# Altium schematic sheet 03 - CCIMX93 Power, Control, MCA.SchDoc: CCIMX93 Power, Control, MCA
size A3; PageSetup: Record=PageOptions¦CenterHorizontal=True¦CenterVertical=True¦PrintScale=0.70¦XCorrection=1.00¦YCorrection=1.00¦PrintKind=0¦BorderSize=5000000¦LeftOffset=0¦BottomOffset=0¦Orientation=2¦PaperLength=4200¦PaperWidth=2970¦Scale=100¦PaperSource=7¦PrintQuality=600¦MediaType=1¦DitherType=10¦PaperKind=A4¦PrintScaleMode=1; Author: Juan Anzola; SheetNumber: 3; SheetTotal: 20
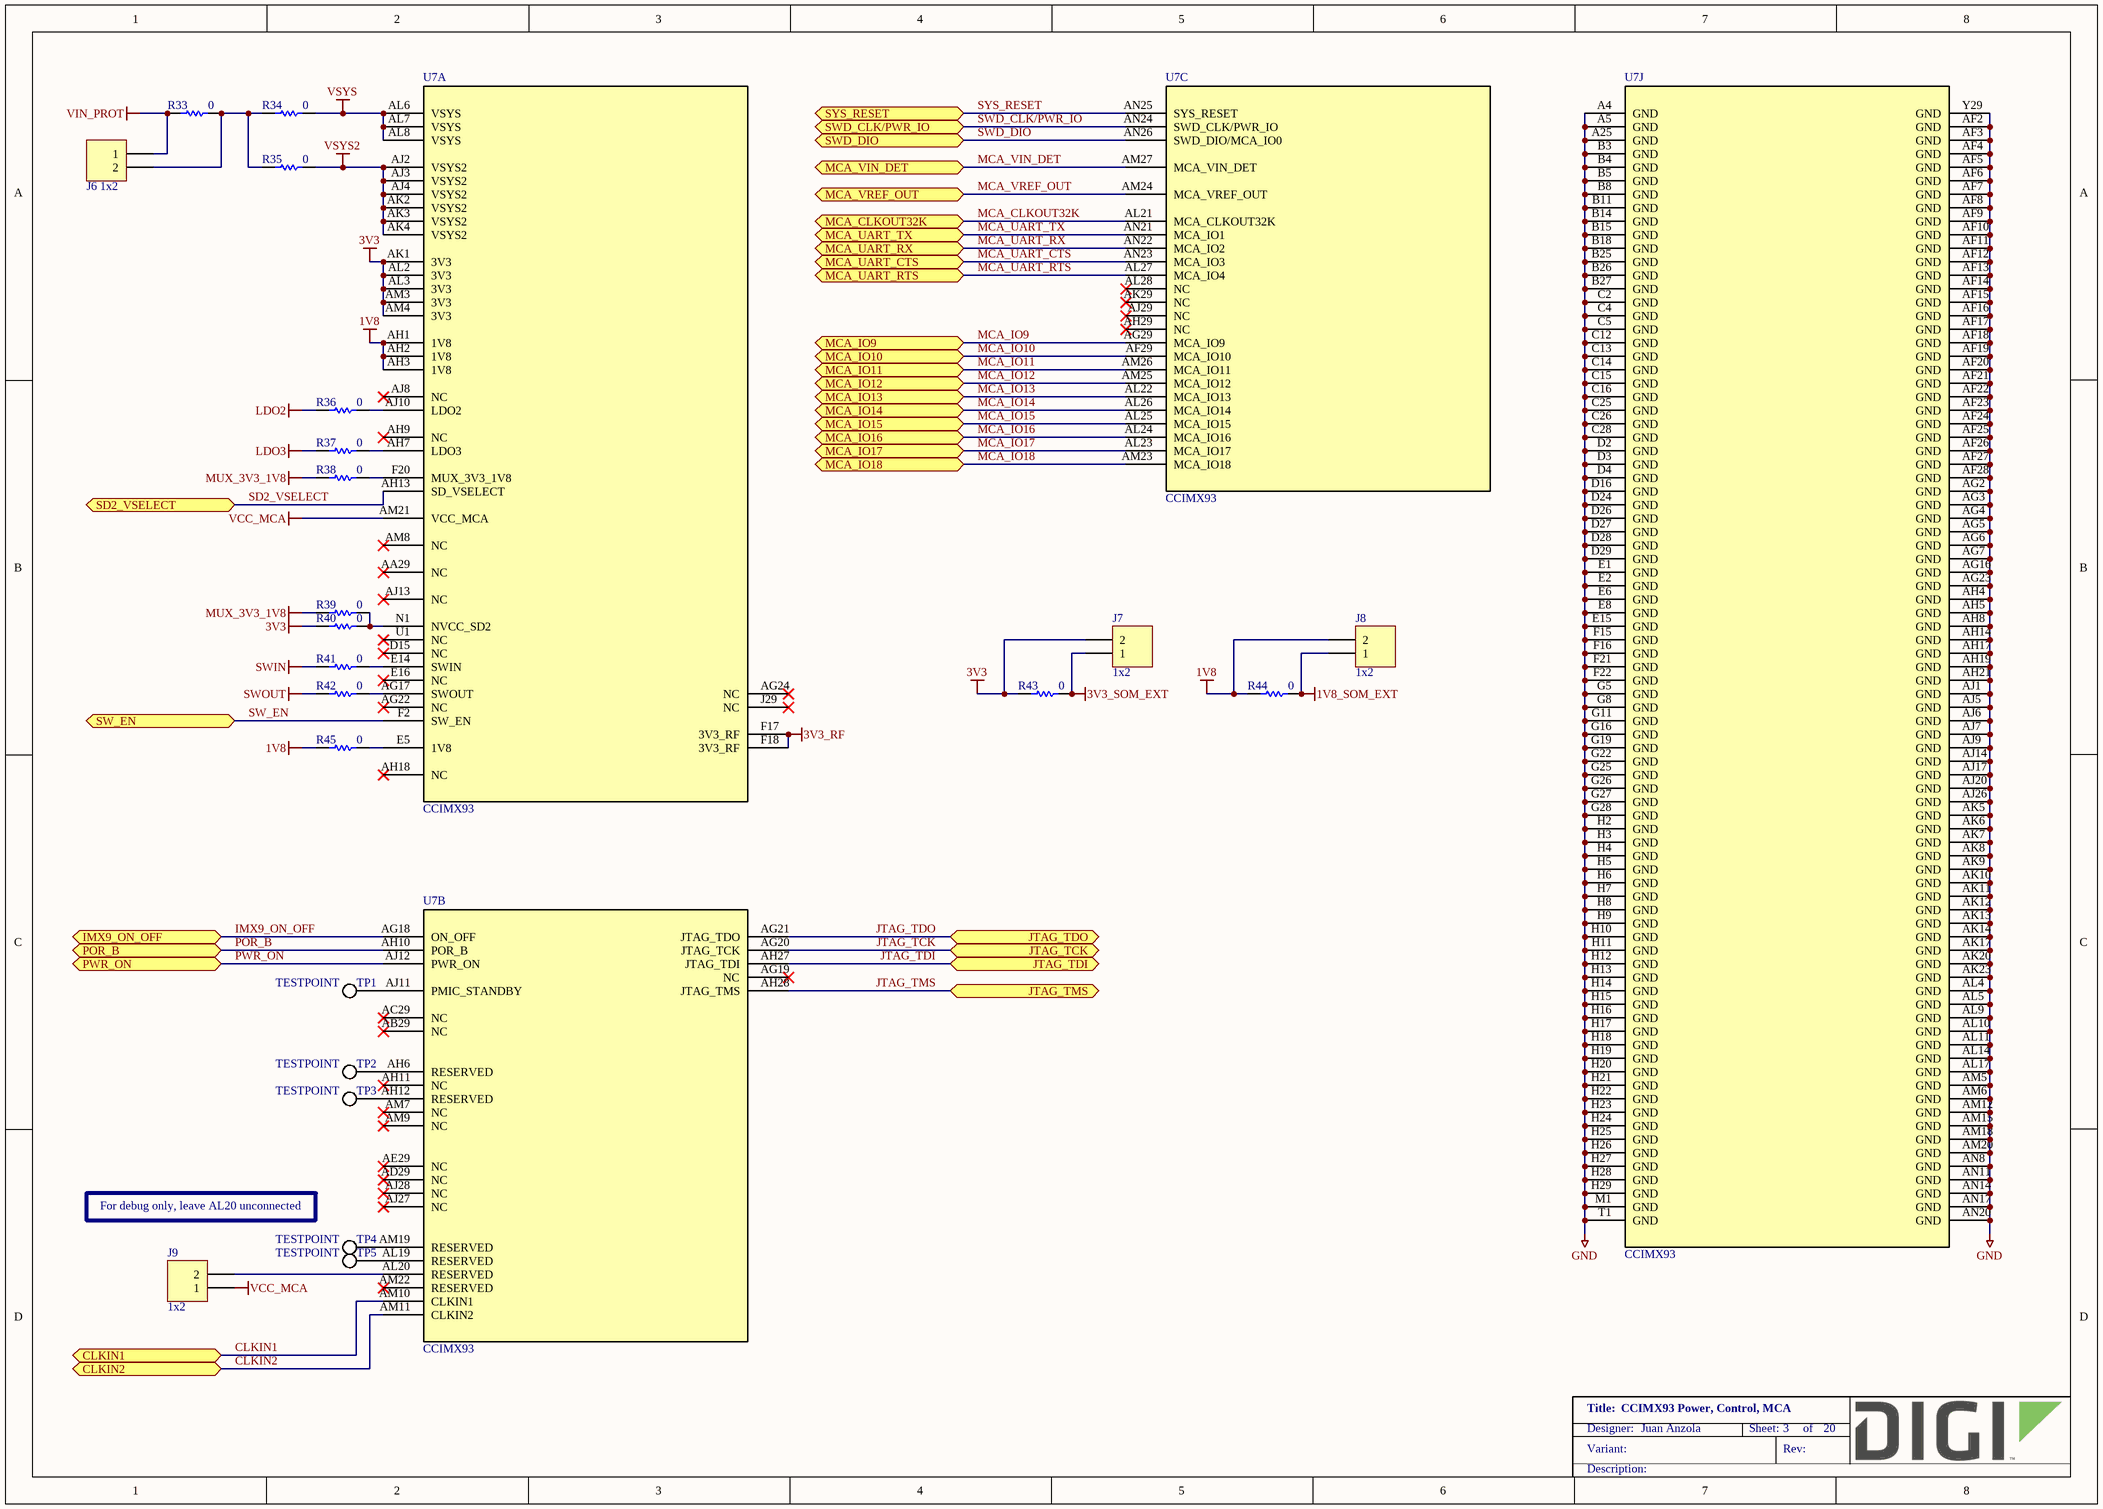
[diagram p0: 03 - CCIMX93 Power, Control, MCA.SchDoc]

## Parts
J6  1x2  [FCI_68002-102HLF]
J7  1x2  [FCI_68002-102HLF]
J8  1x2  [FCI_68002-102HLF]
J9  1x2  [FCI_68002-102HLF]
R33  0  [RESC1609X55N]
R34  0  [RESC1609X55N]
R35  0  [RESC1609X55N]
R36  0  [RESC1005X40N]
R37  0  [RESC1005X40N]
R38  0  [RESC1609X55N]
R39  0  [RESC1005X40N]
R40  0  [RESC1005X40N]
R41  0  [RESC1005X40N]
R42  0  [RESC1005X40N]
R43  0  [RESC1609X55N]
R44  0  [RESC1609X55N]
R45  0  [RESC1005X40N]
TP1  TESTPOINT  [TP0762]  (no BOM)
TP2  TESTPOINT  [TP0762]  (no BOM)
TP3  TESTPOINT  [TP0762]  (no BOM)
TP4  TESTPOINT  [TP0762]  (no BOM)
TP5  TESTPOINT  [TP0762]  (no BOM)
U7  CCIMX93  [CC93_DVK]  (parts A,B,C,J of 10)

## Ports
CLKIN1 (bidir), CLKIN2 (bidir), IMX9_ON_OFF (bidir), JTAG_TCK (bidir), JTAG_TDI (bidir), JTAG_TDO (bidir), JTAG_TMS (bidir), MCA_CLKOUT32K (bidir), MCA_IO9 (bidir), MCA_IO10 (bidir), MCA_IO11 (bidir), MCA_IO12 (bidir), MCA_IO13 (bidir), MCA_IO14 (bidir), MCA_IO15 (bidir), MCA_IO16 (bidir), MCA_IO17 (bidir), MCA_IO18 (bidir), MCA_UART_CTS (bidir), MCA_UART_RTS (bidir), MCA_UART_RX (bidir), MCA_UART_TX (bidir), MCA_VIN_DET (bidir), MCA_VREF_OUT (bidir), POR_B (bidir), PWR_ON (bidir), SD2_VSELECT (bidir), SW_EN (bidir), SWD_CLK/PWR_IO (bidir), SWD_DIO (bidir), SYS_RESET (bidir)

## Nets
1V8: J8.2 R44.1 R45.1 U7.AH1(1V8) U7.AH2(1V8) U7.AH3(1V8)
1V8_SOM_EXT: J8.1 R44.2
3V3: J7.2 R40.1 R43.1 U7.AK1(3V3) U7.AL2(3V3) U7.AL3(3V3) U7.AM3(3V3) U7.AM4(3V3)
3V3_RF: U7.F17(3V3_RF) U7.F18(3V3_RF)
3V3_SOM_EXT: J7.1 R43.2
GND: U7.A25(GND) U7.A4(GND) U7.A5(GND) U7.AF2(GND) U7.AF3(GND) U7.AF4(GND) U7.AF5(GND) U7.AF6(GND) U7.AF7(GND) U7.AF8(GND) U7.AF9(GND) U7.AF10(GND) U7.AF11(GND) U7.AF12(GND) U7.AF13(GND) U7.AF14(GND) U7.AF15(GND) U7.AF16(GND) U7.AF17(GND) U7.AF18(GND) U7.AF19(GND) U7.AF20(GND) U7.AF21(GND) U7.AF22(GND) U7.AF23(GND) U7.AF24(GND) U7.AF25(GND) U7.AF26(GND) U7.AF27(GND) U7.AF28(GND) U7.AG2(GND) U7.AG3(GND) U7.AG4(GND) U7.AG5(GND) U7.AG6(GND) U7.AG7(GND) U7.AG16(GND) U7.AG23(GND) U7.AH4(GND) U7.AH5(GND) U7.AH8(GND) U7.AH14(GND) U7.AH17(GND) U7.AH19(GND) U7.AH21(GND) U7.AJ1(GND) U7.AJ5(GND) U7.AJ6(GND) U7.AJ7(GND) U7.AJ9(GND) U7.AJ14(GND) U7.AJ17(GND) U7.AJ20(GND) U7.AJ26(GND) U7.AK5(GND) U7.AK6(GND) U7.AK7(GND) U7.AK8(GND) U7.AK9(GND) U7.AK10(GND) U7.AK11(GND) U7.AK12(GND) U7.AK13(GND) U7.AK14(GND) U7.AK17(GND) U7.AK20(GND) U7.AK23(GND) U7.AL4(GND) U7.AL5(GND) U7.AL9(GND) U7.AL10(GND) U7.AL11(GND) U7.AL14(GND) U7.AL17(GND) U7.AM5(GND) U7.AM6(GND) U7.AM12(GND) U7.AM15(GND) U7.AM18(GND) U7.AM20(GND) U7.AN8(GND) U7.AN11(GND) U7.AN14(GND) U7.AN17(GND) U7.AN20(GND) U7.B3(GND) U7.B4(GND) U7.B5(GND) U7.B8(GND) U7.B11(GND) U7.B14(GND) U7.B15(GND) U7.B18(GND) U7.B25(GND) U7.B26(GND) U7.B27(GND) U7.C2(GND) U7.C4(GND) U7.C5(GND) U7.C12(GND) U7.C13(GND) U7.C14(GND) U7.C15(GND) U7.C16(GND) U7.C25(GND) U7.C26(GND) U7.C28(GND) U7.D2(GND) U7.D3(GND) U7.D4(GND) U7.D16(GND) U7.D24(GND) U7.D26(GND) U7.D27(GND) U7.D28(GND) U7.D29(GND) U7.E1(GND) U7.E2(GND) U7.E6(GND) U7.E8(GND) U7.E15(GND) U7.F15(GND) U7.F16(GND) U7.F21(GND) U7.F22(GND) U7.G5(GND) U7.G8(GND) U7.G11(GND) U7.G16(GND) U7.G19(GND) U7.G22(GND) U7.G25(GND) U7.G26(GND) U7.G27(GND) U7.G28(GND) U7.H2(GND) U7.H3(GND) U7.H4(GND) U7.H5(GND) U7.H6(GND) U7.H7(GND) U7.H8(GND) U7.H9(GND) U7.H10(GND) U7.H11(GND) U7.H12(GND) U7.H13(GND) U7.H14(GND) U7.H15(GND) U7.H16(GND) U7.H17(GND) U7.H18(GND) U7.H19(GND) U7.H20(GND) U7.H21(GND) U7.H22(GND) U7.H23(GND) U7.H24(GND) U7.H25(GND) U7.H26(GND) U7.H27(GND) U7.H28(GND) U7.H29(GND) U7.M1(GND) U7.T1(GND) U7.Y29(GND)
LDO2: R36.1
LDO3: R37.1
MUX_3V3_1V8: R38.1 R39.1
SWIN: R41.1
SWOUT: R42.1
VCC_MCA: J9.1 U7.AM21(VCC_MCA)
VIN_PROT: J6.1 R33.1
VSYS: R34.2 U7.AL6(VSYS) U7.AL7(VSYS) U7.AL8(VSYS)
VSYS2: R35.2 U7.AJ2(VSYS2) U7.AJ3(VSYS2) U7.AJ4(VSYS2) U7.AK2(VSYS2) U7.AK3(VSYS2) U7.AK4(VSYS2)
CLKIN1: U7.AM10(CLKIN1) ; port CLKIN1
CLKIN2: U7.AM11(CLKIN2) ; port CLKIN2
IMX9_ON_OFF: U7.AG18(ON_OFF) ; port IMX9_ON_OFF
JTAG_TCK: U7.AG20(JTAG_TCK) ; port JTAG_TCK
JTAG_TDI: U7.AH27(JTAG_TDI) ; port JTAG_TDI
JTAG_TDO: U7.AG21(JTAG_TDO) ; port JTAG_TDO
JTAG_TMS: U7.AH28(JTAG_TMS) ; port JTAG_TMS
MCA_CLKOUT32K: U7.AL21(MCA_CLKOUT32K) ; port MCA_CLKOUT32K
MCA_IO9: U7.AG29(MCA_IO9) ; port MCA_IO9
MCA_IO10: U7.AF29(MCA_IO10) ; port MCA_IO10
MCA_IO11: U7.AM26(MCA_IO11) ; port MCA_IO11
MCA_IO12: U7.AM25(MCA_IO12) ; port MCA_IO12
MCA_IO13: U7.AL22(MCA_IO13) ; port MCA_IO13
MCA_IO14: U7.AL26(MCA_IO14) ; port MCA_IO14
MCA_IO15: U7.AL25(MCA_IO15) ; port MCA_IO15
MCA_IO16: U7.AL24(MCA_IO16) ; port MCA_IO16
MCA_IO17: U7.AL23(MCA_IO17) ; port MCA_IO17
MCA_IO18: U7.AM23(MCA_IO18) ; port MCA_IO18
MCA_UART_CTS: U7.AN23(MCA_IO3) ; port MCA_UART_CTS
MCA_UART_RTS: U7.AL27(MCA_IO4) ; port MCA_UART_RTS
MCA_UART_RX: U7.AN22(MCA_IO2) ; port MCA_UART_RX
MCA_UART_TX: U7.AN21(MCA_IO1) ; port MCA_UART_TX
MCA_VIN_DET: U7.AM27(MCA_VIN_DET) ; port MCA_VIN_DET
MCA_VREF_OUT: U7.AM24(MCA_VREF_OUT) ; port MCA_VREF_OUT
POR_B: U7.AH10(POR_B) ; port POR_B
PWR_ON: U7.AJ12(PWR_ON) ; port PWR_ON
SD2_VSELECT: U7.AH13(SD_VSELECT) ; port SD2_VSELECT
SW_EN: U7.F2(SW_EN) ; port SW_EN
SWD_CLK/PWR_IO: U7.AN24(SWD_CLK/PWR_IO) ; port SWD_CLK/PWR_IO
SWD_DIO: U7.AN26(SWD_DIO/MCA_IO0) ; port SWD_DIO
SYS_RESET: U7.AN25(SYS_RESET) ; port SYS_RESET
NetJ6_2: J6.2 R33.2 R34.1 R35.1
NetJ9_2: J9.2 U7.AL20(RESERVED)
NetR36_2: R36.2 U7.AJ10(LDO2)
NetR37_2: R37.2 U7.AH7(LDO3)
NetR38_2: R38.2 U7.F20(MUX_3V3_1V8)
NetR39_2: R39.2 R40.2 U7.N1(NVCC_SD2)
NetR41_2: R41.2 U7.E14(SWIN)
NetR42_2: R42.2 U7.AG17(SWOUT)
NetR45_2: R45.2 U7.E5(1V8)
NetTP1_1: TP1.1 U7.AJ11(PMIC_STANDBY)
NetTP2_1: TP2.1 U7.AH6(RESERVED)
NetTP3_1: TP3.1 U7.AH12(RESERVED)
NetTP4_1: TP4.1 U7.AM19(RESERVED)
NetTP5_1: TP5.1 U7.AL19(RESERVED)

Not connected (* = marked no-connect by the designer): U7 AA29(NC)* AB29(NC)* AC29(NC)* AD29(NC)* AE29(NC)* AG19(NC)* AG22(NC)* AG24(NC)* AH9(NC)* AH11(NC)* AH18(NC)* AH29(NC)* AJ8(NC)* AJ13(NC)* AJ27(NC)* AJ28(NC)* AJ29(NC)* AK29(NC)* AL28(NC)* AM7(NC)* AM8(NC)* AM9(NC)* AM22(RESERVED)* D15(NC)* E16(NC)* J29(NC)* U1(NC)*

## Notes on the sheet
- For debug only, leave AL20 unconnected

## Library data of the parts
J6-J9 = 1001128: CONN HEADER 2POS .100" SGL GOLD; Part_Type: Connector; Manufacturer: Samtec; Manufacturer_Part_Number: TSW-102-07-G-S; Digi_PN: 00120002; Component_Life_Cycle_State: Reviewed; Area: 12,9032
R33 = 1000208: RES 0.0 OHM 1/10W 0603; Part_Type: Resistor; Manufacturer: Panasonic - ECG; Manufacturer_Part_Number: ERJ-3GEY0R00V; Note: 13051103 = Digi No. for GE WDNU; Digi_PN: 13050568; Component_Life_Cycle_State: Reviewed; Area: 2,5; Voltage: 75V
R34 R35 R38 R43 R44 = 1000208: RES 0.0 OHM 1/10W 0603; Part_Type: Resistor; Manufacturer: Panasonic - ECG; Manufacturer_Part_Number: ERJ-3GEY0R00V; Note: 13051103 = Digi No. for GE WDNU; Digi_PN: 13050568; Component_Life_Cycle_State: Reviewed; Area: 2,5; Project: Adjustable Foundation; Voltage: 75V
R36 R37 R39-R42 R45 = 1000076: RES 0.0 OHM 1/10W 0402 SMD; Part_Type: Resistor; Manufacturer: Panasonic - ECG; Manufacturer_Part_Number: ERJ-2GE0R00X; Digi_PN: 13050387; Component_Life_Cycle_State: Proven; Area: 0,95; Power_WV_SRF: 10
TP1-TP5 = CAD0011: TEST POINT 30MIL PAD SMT; Component_Life_Cycle_State: Reviewed; Area: 0,58; Project: CLC
U7 = 1002856: ConnectCore for i.MX93 module; Manufacturer: DIGI; Digi_PN: 55002169-01; Component_Life_Cycle_State: Pending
